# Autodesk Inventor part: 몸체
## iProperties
Company: 한국ATC센터
Created: 2012-05
Part Number: 몸체
Document SubType Name: 모델링
Designer: KYOUNG IL JANG
Mass: 471.062 g
Surface Area: 679.308 cm^2
Volume: 173.824 cm^3
Density: 2.71 g/cm^3
Material: 알루미늄-6061
변환 표준: STEP AP214IS
파일 이름: C:\Users\SeoGD\Desktop\?쒗뿕\紐몄껜.stp
전처리기: Build: 253, Release: 2010 SP1 - Date: Wed 07/29/2009
전송 단위: 밀리미터
불확실성: 0.01
Author: KYOUNG IL JANG
